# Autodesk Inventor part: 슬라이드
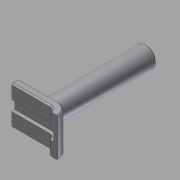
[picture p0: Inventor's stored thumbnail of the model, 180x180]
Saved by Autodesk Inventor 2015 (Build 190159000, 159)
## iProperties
Created: 2015-10
Part Number: 슬라이드
Document SubType Name: Modeling
Designer: mdu
Density: 7.86 g/cm^3
Material: 강철, 연강
Mass: 21.364 g
Surface Area: 19.6411 cm^2
Volume: 2.71806 cm^3
Appearance: 기본값
Author: mdu
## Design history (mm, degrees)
sketch "스케치1"
  geometry: L1 (10.279, 23.212)-(25.279, 23.212); L2 (10.279, 19.212)-(25.279, 19.212); L3 (25.279, 26.212)-(10.279, 26.212); L4 (10.279, 26.212)-(10.279, 16.212); L5 (10.279, 16.212)-(25.279, 16.212); C1 r 2 at (25.279, 21.212); A1 r 2 centre (25.279, 21.212) between (25.279, 23.212) and (25.279, 19.212) reference; A2 r 5 centre (25.279, 21.212) between (25.279, 26.212) and (25.279, 16.212); 1 further point
  constraints: 10 end point, 4 point on circle, 4 tangent, 3 parallel, 2 centre point, 2 coincident, 2 point on line, 1 horizontal, 1 perpendicular
  dimensions: "d0" = 4 diameter of C1; "d1" = 10 diameter of A2; "d4" = 15 distance from line of A2.centre L4
extrude "돌출1" new body sketch "스케치1" stored distance "d2" = 15; taper "d3" = 0 deg
sketch "스케치2"
  geometry: L1 (10.279, 26.212)-(10.279, 23.212) reference; L2 (10.279, 24.462)-(25.279, 24.462); L3 (27.779, 19.135)-(27.779, 6.212); L4 (27.779, 6.212)-(0.279, 6.212); L5 (0.279, 6.212)-(0.279, 24.462); L6 (10.279, 24.462)-(0.279, 24.462); A1 r 5 centre (25.279, 21.212) between (25.279, 16.212) and (25.279, 26.212) reference; A2 r 3.25 centre (25.279, 21.212) between (25.279, 24.462) and (27.779, 19.135); 1 further point
  constraints: 10 end point, 4 perpendicular, 2 point on circle, 1 centre point, 1 coincident, 1 parallel, 1 point on line, 1 tangent
  dimensions: "d5" = 6.5 diameter of A2; "d6" = 10 distance between parallel lines of L1 L5; "d7" = 10 distance from line of L4 A1.start; "d8" = 2.5 distance from line of L3 A1.centre
extrude "돌출2" cut sketch "스케치2" stored distance "d9" = 4; taper "d10" = 0 deg
sketch "스케치3"
  geometry: L1 (0, 15)-(0, 0) reference; C1 r 4 at (9.5, 7.5); 2 further points
  constraints: 1 centre point, 1 horizontal alignment, 1 midpoint
  dimensions: "d11" = 8 diameter of C1; "d12" = 9.5 distance from line of C1.centre L1
extrude "돌출3" join sketch "스케치3" distance "d13" = 40; taper "d14" = 0 deg
sketch "스케치4"
  geometry: C1 r 4 at (9.5, 7.5) reference; C2 r 4.65 at (9.5, 7.5); C3 r 6.75 at (9.5, 7.5); C4 r 5.5 at (9.5, 7.5); 1 further point
  constraints: 3 centre point, 3 coincident
  dimensions: "d15" = 9.3 diameter of C2; "d16" = 13.5 diameter of C3; "d19" = 11 diameter of C4
extrude "돌출4" cut sketch "스케치4" distance "d17" = 0.5; taper "d18" = 0 deg
sketch "스케치5"
  geometry: L1 (30.279, 21.212)-(7.279, 21.212); L2 (7.279, 21.212)-(7.279, 13.212); L3 (7.279, 13.212)-(31.947, 13.212); L4 (31.947, 13.212)-(31.947, 21.212); L5 (31.947, 21.212)-(30.279, 21.212); L6 (10.279, 16.212)-(10.279, 19.212) reference; A1 r 5 centre (25.279, 21.212) between (25.279, 16.212) and (25.279, 26.212) reference; 1 further point
  constraints: 10 end point, 2 perpendicular, 1 collinear, 1 horizontal, 1 parallel, 1 point on circle
  dimensions: "d20" = 3 distance between parallel lines of L2 L6; "d21" = 8 distance of L3.end L4.end
extrude "돌출5" cut sketch "스케치5" stored distance "d22" = 1; taper "d23" = 0 deg
chamfer "모따기1" distance "d24" = 0.5; stored, may be unused: second distance "d25" = 2, angle "d26" = 45 deg
hole "구멍1" diameter "d29" = 3.242; stored, may be unused: countersink angle "d33" = 90 deg, drill point angle "d35" = 118 deg; dims "d27" = 10, "d28" = 10, "d30" = 6, "d31" = 4, "d32" = 2, "d34" = 8
chamfer "모따기2" distance "d36" = 0.5; stored, may be unused: second distance "d37" = 2, angle "d38" = 45 deg
node "솔리드1"
node "참조1"
node "투영된 루프1"
